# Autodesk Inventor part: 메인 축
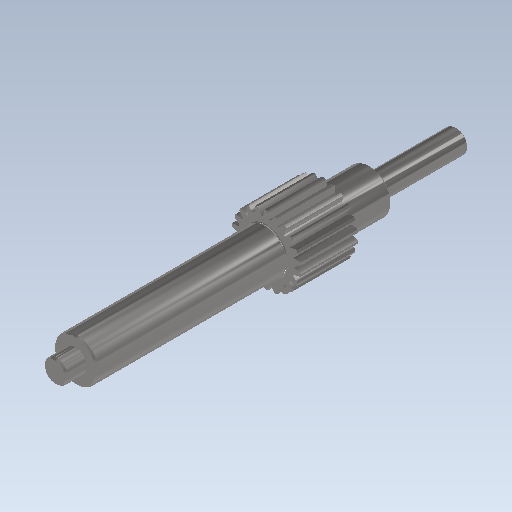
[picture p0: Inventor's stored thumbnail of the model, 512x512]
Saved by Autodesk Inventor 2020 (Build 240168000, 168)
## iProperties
Created: 2016-02
Part Number: 메인 축
Material: 강철, 연강
Document SubType Name: Modeling
Categories: <?xml version="1.0" encoding="UTF-16"?> <MemberInstance><Categories><FamilyTemplate><FamilyTemplateParameter ValueType="xs:double" Id="1" ObjectReferenceKey="da
Density: 7.86 g/cm^3
Mass: 187.503 g
Surface Area: 82.0529 cm^2
Volume: 23.8554 cm^3
Appearance: 강철 - 광택
Author: mdu
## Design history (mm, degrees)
sketch "Sketch1"
  geometry: C1 r 12 at (0, 0)
  constraints: 1 centre point
  dimensions: "d0" = 24 diameter of C1 (= da_da)
extrude "Extrusion1" new body sketch "Sketch1" distance "d1" = 20 (= da_b); taper "d2" = 0 deg
workplane "Work Plane2"
feature "피치 지름" dims "d4" = 10, "d5" = 0
workplane "Work Plane8"
workplane "Work Plane9"
chamfer "모따기1" distance "d49" = 0.2; stored, may be unused: second distance "d50" = 2, angle "d51" = 45 deg
sketch "스케치3"
  geometry: C1 r 7.5 at (0, 0); 1 further point
  constraints: 1 centre point, 1 coincident
  dimensions: "d52" = 15 diameter of C1
extrude "돌출2" join sketch "스케치3" distance "d53" = 66; taper "d54" = 0 deg
sketch "스케치4"
  geometry: C1 r 4 at (0, 0); 1 further point
  constraints: 1 centre point, 1 coincident
  dimensions: "d55" = 8 diameter of C1
extrude "돌출3" join sketch "스케치4" distance "d56" = 7; taper "d57" = 0 deg
sketch "스케치5"
  geometry: C1 r 7.5 at (0, 0) reference; C2 r 7.5 at (0, 0) reference; 1 further point
extrude "돌출4" join sketch "스케치5" distance "d62" = 16; taper "d63" = 0 deg
sketch "스케치6"
  geometry: C1 r 4 at (0, 0); 1 further point
  constraints: 1 centre point, 1 coincident
  dimensions: "d64" = 8 diameter of C1
extrude "돌출5" join sketch "스케치6" distance "d65" = 30; taper "d66" = 0 deg
chamfer "모따기2" distance "d58" = 0.5; stored, may be unused: second distance "d59" = 2, angle "d60" = 45 deg
fillet "모깎기1" dims "d61" = 0.5
feature "스퍼 기어" dims "da_b" = 20, "da_d" = 22, "da_aw" = 31, "da_da" = 24, "da_df" = 19.5, "da_dw" = 22, angle "da_beta" = 0 deg, "da_lefttooth" = 0, "da_righttooth" = 0
sketch "스케치7" dims "d68" = 18
  geometry: C1 r 0.25 at (0, -9); 2 further points
  constraints: 2 vertical alignment, 1 centre point, 1 coincident, 2 other
  dimensions: "d67" = 0.5 diameter of C1
extrude "돌출6" join sketch "스케치7" distance "d69" = 0.3; taper "d70" = 0 deg
body "Solid1"
sketch "Sketch2"
  geometry: C1 r 12 at (0, 0) reference; C2 r 11 at (0, 0)
  constraints: 1 centre point, 1 coincident
  dimensions: "d3" = 22 diameter of C2 (= da_dw)
body "Srf1"
node "투영된 루프1"
other parameters: "d16" = 31 (= da_aw), "d17" = 0, "d34" = 1.428 (computed from da_z), "d39" = 0, "d41" = 0, "d43" = 31 (= da_aw), "d46" = 31 (= da_aw), "d47" = 0, "d48" = 0
